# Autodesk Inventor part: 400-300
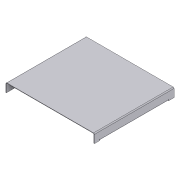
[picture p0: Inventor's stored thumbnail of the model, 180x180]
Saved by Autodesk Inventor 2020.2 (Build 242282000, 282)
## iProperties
Created: 2010-10
Part Number: 400-300
Material: St1203
Document SubType Name: Konstrukcje blachowe
Designer: F.Stasiak
Density: 7.85 g/cm^3
Sheet Metal Rule: Blacha stalowa 2.5 mm/Okrągły
Description: =Ściana prawa <WYSOKOŚĆ> x <SZEROKOŚĆ> pełna
Appearance: Metal-Stal
Mass: 5414.52 g
Surface Area: 5573.85 cm^2
Volume: 689.747 cm^3
Company: Fabian Stasiak CAD Consulting
Manager: www.cadconsulting.pl
SZEROKOŚĆ: 500
WYSOKOŚĆ: 450
Author: F.Stasiak
Subject: Zbiór ćwiczeń. Autodesk Inventor 2020. Kurs podstawowy
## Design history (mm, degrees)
node "Powierzchnia1"
  sketch "Szkic1"
    geometry: L1 (-250, 450)-(250, 450); L2 (250, 450)-(250, 0); L3 (250, 0)-(-250, 0); L4 (-250, 0)-(-250, 450); 2 further points
    constraints: 8 end point, 2 parallel, 1 coincident, 1 horizontal, 1 midpoint, 1 perpendicular
    dimensions: "d0" = 500 distance of L2.end L3.end; "d1" = 450 distance of L1.end L2.end
node "Kołnierz1"
node "Kołnierz2"
feature "Zawinięcie obrzeża1" dims "d25" = 2.5 (= SzerokośćGięciaPodcięcia), "d26" = 1.25 (= GłębokośćGięciaPodcięcia), "d27" = 5 (= MinimalnaPozostałość), "d28" = 2.5 (= PromieńGięcia), "d29" = 10 (= 4 x Grubość), "d30" = 1.25 (= 0.5 x Grubość), "d31" = 0.625 (= 0.5 x d30), "d54" = 2.5 (= Grubość), "OdstępPołączenia" = 0.01
sketch "Szkic6"
  geometry: L1 (-45, 450)-(-45, 0) reference; L2 (0, 0)-(-45, 0) reference; L3 (0, 0)-(0, 450) reference; L4 (0, 450)-(-45, 450) reference; L5 (-22.5, 0)-(-22.5, 450); 3 further points
  constraints: 2 end point, 2 midpoint, 2 point on line
  dimensions: "d45" = 130 distance from line of L2 point (-22.5, 130); "d46" = 150 distance from line of L4 point (-22.5, 300)
hole "Hole1" sketch "Szkic6" at (-22.5, 130), (-22.5, 300) diameter "d47" = 12; stored, may be unused: countersink angle "d51" = 90 deg, drill point angle "d53" = 118 deg; dims "d48" = 6, "d49" = 4, "d50" = 2, "d52" = 2.5 (= Grubość)
node "Bryła1"
feature "Płyta1" dims "d54" = 2.5 (= Grubość)
sketch "Szkic2"
  geometry: L1 (0, -50)-(450, -50); L2 (450, -50)-(450, 0); 1 other entity
  constraints: 4 end point, 4 other
feature "Płyta2" dims "d3" = 2.5 (= SzerokośćGięciaPodcięcia), "d4" = 1.25 (= GłębokośćGięciaPodcięcia), "d5" = 5 (= MinimalnaPozostałość), "d6" = 2.5 (= PromieńGięcia), "d7" = 50, "d8" = 90 deg, "d9" = 2.5 (= PromieńGięcia), "d10" = 10 (= RozmiarPodcięciaNarożnika), "d11" = 2.5 (= Wielk_odstępu), "d12" = 2.5 (= Rozmiar_promienia_Jacobiego), "d54" = 2.5 (= Grubość), "OdstępPołączenia" = 0.01
feature "Gięcie1" dims "d3" = 2.5 (= SzerokośćGięciaPodcięcia), "d4" = 1.25 (= GłębokośćGięciaPodcięcia), "d5" = 5 (= MinimalnaPozostałość), "d6" = 2.5 (= PromieńGięcia), "d7" = 50, "d8" = 90 deg, "d9" = 2.5 (= PromieńGięcia), "d54" = 2.5 (= Grubość), "OdstępPołączenia" = 0.01
feature "Narożnik1" dims "d7" = 50, "d8" = 90 deg, "d10" = 10 (= RozmiarPodcięciaNarożnika), "d11" = 2.5 (= Wielk_odstępu), "d12" = 2.5 (= Rozmiar_promienia_Jacobiego)
sketch "Szkic3"
  geometry: L1 (0, 418)-(0, 32); L2 (0, 32)-(20, 32); L3 (20, 32)-(20, 418); L4 (20, 418)-(0, 418)
  constraints: 8 end point
feature "Płyta3" dims "d13" = 2.5 (= SzerokośćGięciaPodcięcia), "d14" = 1.25 (= GłębokośćGięciaPodcięcia), "d15" = 5 (= MinimalnaPozostałość), "d16" = 2.5 (= PromieńGięcia), "d17" = 32, "d18" = 32, "d19" = 20, "d20" = 90 deg, "d21" = 2.5 (= PromieńGięcia), "d22" = 10 (= RozmiarPodcięciaNarożnika), "d23" = 2.5 (= Wielk_odstępu), "d24" = 2.5 (= Rozmiar_promienia_Jacobiego), "d54" = 2.5 (= Grubość), "OdstępPołączenia" = 0.01
feature "Gięcie2" dims "d13" = 2.5 (= SzerokośćGięciaPodcięcia), "d14" = 1.25 (= GłębokośćGięciaPodcięcia), "d15" = 5 (= MinimalnaPozostałość), "d16" = 2.5 (= PromieńGięcia), "d19" = 20, "d20" = 90 deg, "d21" = 2.5 (= PromieńGięcia), "d54" = 2.5 (= Grubość), "OdstępPołączenia" = 0.01
feature "Narożnik2" dims "d19" = 20, "d20" = 90 deg, "d22" = 10 (= RozmiarPodcięciaNarożnika), "d23" = 2.5 (= Wielk_odstępu), "d24" = 2.5 (= Rozmiar_promienia_Jacobiego)
node "Pętla rzutowana1"
sketch "Szkic4"
  geometry: L1 (0, -2.5)-(0, 0); L2 (0, 1.25)-(-6.875, 1.25); L3 (-6.875, 1.25)-(-6.875, 3.75); L4 (-6.875, 3.75)-(0, 3.75); A1 r 0.625 centre (0, 0.625) between (0, 0) and (0, 1.25); A2 r 3.125 centre (0, 0.625) between (0, -2.5) and (0, 3.75)
  constraints: 8 end point, 4 point on circle
other parameters: "Grubość" = 2.5 (derived), "WspółczynnikK" = 4.4, "PromieńGięcia" = 2.5 (= Grubość), "SzerokośćGięciaPodcięcia" = 2.5 (= Grubość), "GłębokośćGięciaPodcięcia" = 1.25 (= 0.5 x Grubość), "MinimalnaPozostałość" = 5 (= 2 x Grubość), "PromieńPrzejścia" = 2.5 (= PromieńGięcia), "Rozmiar_promienia_Jacobiego" = 2.5 (= PromieńGięcia), "Wielk_odstępu" = 2.5 (= Grubość), "d2" = 2.5 (= PromieńGięcia)
